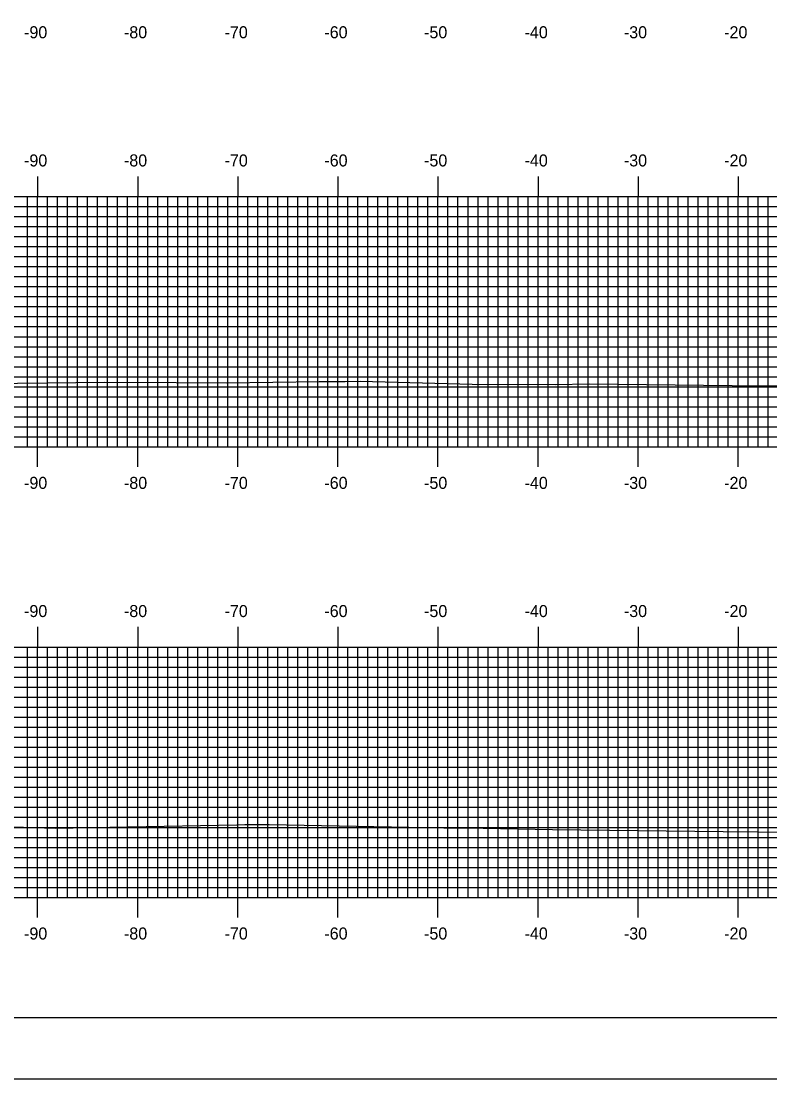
# Model space of a CAD drawing. Extents: x 856323 to 856666, y 364765 to 364985.
# Drawn here: x 856397.1 to 856471.9, y 364765.2 to 364870.8 of the extents above; entities that cross this region are included whole.
import ezdxf

# ---------------------------------------------------------------- set-up
doc = ezdxf.new("R2010")
doc.units = 0
for name, color, linetype in [('BORDER', 7, 'Continuous'), ('H_V ANNOTATION', 7, 'Continuous'), ('MAJOR', 7, 'Continuous'), ('MINOR', 7, 'Continuous'), ('PLOT BOUNDARY', 7, 'Continuous'), ('S_Roadway_Centerline', 7, 'Continuous')]:
    doc.layers.add(name, color=color, linetype=linetype)

msp = doc.modelspace()

# ---------------------------------------------------------------- linework, layer by layer
at = {"layer": 'BORDER'}
msp.add_lwpolyline([(856339.17, 364771.3), (856659.17, 364771.3), (856659.17, 364981.3), (856339.17, 364981.3)], close=True, dxfattribs=at)
at = {"layer": 'MAJOR'}
for p, q in [((856398.77, 364855.31), (856398.77, 364853.3)), ((856408.77, 364855.31), (856408.77, 364853.3)), ((856418.77, 364855.31), (856418.77, 364853.3)), ((856428.77, 364855.31), (856428.77, 364853.3)), ((856438.77, 364855.31), (856438.77, 364853.3)), ((856448.77, 364855.31), (856448.77, 364853.3)), ((856458.77, 364855.31), (856458.77, 364853.3)), ((856468.77, 364855.31), (856468.77, 364853.3)), ((856348.77, 364853.3), (856628.77, 364853.3)), ((856348.77, 364853.3), (856628.77, 364853.3)), ((856398.77, 364828.3), (856398.77, 364853.3)), ((856408.77, 364828.3), (856408.77, 364853.3)), ((856418.77, 364828.3), (856418.77, 364853.3)), ((856428.77, 364828.3), (856428.77, 364853.3)), ((856438.77, 364828.3), (856438.77, 364853.3)), ((856448.77, 364828.3), (856448.77, 364853.3)), ((856458.77, 364828.3), (856458.77, 364853.3)), ((856468.77, 364828.3), (856468.77, 364853.3)), ((856348.77, 364848.3), (856628.77, 364848.3)), ((856348.77, 364843.3), (856628.77, 364843.3)), ((856348.77, 364838.3), (856628.77, 364838.3)), ((856348.77, 364833.3), (856628.77, 364833.3)), ((856348.77, 364828.3), (856628.77, 364828.3)), ((856348.77, 364828.3), (856628.77, 364828.3)), ((856398.77, 364826.3), (856398.77, 364828.3)), ((856408.77, 364826.3), (856408.77, 364828.3)), ((856418.77, 364826.3), (856418.77, 364828.3)), ((856428.77, 364826.3), (856428.77, 364828.3)), ((856438.77, 364826.3), (856438.77, 364828.3)), ((856448.77, 364826.3), (856448.77, 364828.3)), ((856458.77, 364826.3), (856458.77, 364828.3)), ((856468.77, 364826.3), (856468.77, 364828.3)), ((856398.77, 364810.31), (856398.77, 364808.3)), ((856408.77, 364810.31), (856408.77, 364808.3)), ((856418.77, 364810.31), (856418.77, 364808.3)), ((856428.77, 364810.31), (856428.77, 364808.3)), ((856438.77, 364810.31), (856438.77, 364808.3)), ((856448.77, 364810.31), (856448.77, 364808.3)), ((856458.77, 364810.31), (856458.77, 364808.3)), ((856468.77, 364810.31), (856468.77, 364808.3)), ((856348.77, 364808.3), (856628.77, 364808.3)), ((856348.77, 364808.3), (856628.77, 364808.3)), ((856398.77, 364783.3), (856398.77, 364808.3)), ((856408.77, 364783.3), (856408.77, 364808.3)), ((856418.77, 364783.3), (856418.77, 364808.3)), ((856428.77, 364783.3), (856428.77, 364808.3)), ((856438.77, 364783.3), (856438.77, 364808.3)), ((856448.77, 364783.3), (856448.77, 364808.3)), ((856458.77, 364783.3), (856458.77, 364808.3)), ((856468.77, 364783.3), (856468.77, 364808.3)), ((856348.77, 364803.3), (856628.77, 364803.3)), ((856348.77, 364798.3), (856628.77, 364798.3)), ((856348.77, 364793.3), (856628.77, 364793.3)), ((856348.77, 364788.3), (856628.77, 364788.3)), ((856348.77, 364783.3), (856628.77, 364783.3)), ((856348.77, 364783.3), (856628.77, 364783.3)), ((856398.77, 364781.3), (856398.77, 364783.3)), ((856408.77, 364781.3), (856408.77, 364783.3)), ((856418.77, 364781.3), (856418.77, 364783.3)), ((856428.77, 364781.3), (856428.77, 364783.3)), ((856438.77, 364781.3), (856438.77, 364783.3)), ((856448.77, 364781.3), (856448.77, 364783.3)), ((856458.77, 364781.3), (856458.77, 364783.3)), ((856468.77, 364781.3), (856468.77, 364783.3))]:
    msp.add_line(p, q, dxfattribs=at)
at = {"layer": 'MINOR'}
for p, q in [((856397.77, 364828.3), (856397.77, 364853.3)), ((856399.77, 364828.3), (856399.77, 364853.3)), ((856400.77, 364828.3), (856400.77, 364853.3)), ((856401.77, 364828.3), (856401.77, 364853.3)), ((856402.77, 364828.3), (856402.77, 364853.3)), ((856403.77, 364828.3), (856403.77, 364853.3)), ((856404.77, 364828.3), (856404.77, 364853.3)), ((856405.77, 364828.3), (856405.77, 364853.3)), ((856406.77, 364828.3), (856406.77, 364853.3)), ((856407.77, 364828.3), (856407.77, 364853.3)), ((856409.77, 364828.3), (856409.77, 364853.3)), ((856410.77, 364828.3), (856410.77, 364853.3)), ((856411.77, 364828.3), (856411.77, 364853.3)), ((856412.77, 364828.3), (856412.77, 364853.3)), ((856413.77, 364828.3), (856413.77, 364853.3)), ((856414.77, 364828.3), (856414.77, 364853.3)), ((856415.77, 364828.3), (856415.77, 364853.3)), ((856416.77, 364828.3), (856416.77, 364853.3)), ((856417.77, 364828.3), (856417.77, 364853.3)), ((856419.77, 364828.3), (856419.77, 364853.3)), ((856420.77, 364828.3), (856420.77, 364853.3)), ((856421.77, 364828.3), (856421.77, 364853.3)), ((856422.77, 364828.3), (856422.77, 364853.3)), ((856423.77, 364828.3), (856423.77, 364853.3)), ((856424.77, 364828.3), (856424.77, 364853.3)), ((856425.77, 364828.3), (856425.77, 364853.3)), ((856426.77, 364828.3), (856426.77, 364853.3)), ((856427.77, 364828.3), (856427.77, 364853.3)), ((856429.77, 364828.3), (856429.77, 364853.3)), ((856430.77, 364828.3), (856430.77, 364853.3)), ((856431.77, 364828.3), (856431.77, 364853.3)), ((856432.77, 364828.3), (856432.77, 364853.3)), ((856433.77, 364828.3), (856433.77, 364853.3)), ((856434.77, 364828.3), (856434.77, 364853.3)), ((856435.77, 364828.3), (856435.77, 364853.3)), ((856436.77, 364828.3), (856436.77, 364853.3)), ((856437.77, 364828.3), (856437.77, 364853.3)), ((856439.77, 364828.3), (856439.77, 364853.3)), ((856440.77, 364828.3), (856440.77, 364853.3)), ((856441.77, 364828.3), (856441.77, 364853.3)), ((856442.77, 364828.3), (856442.77, 364853.3)), ((856443.77, 364828.3), (856443.77, 364853.3)), ((856444.77, 364828.3), (856444.77, 364853.3)), ((856445.77, 364828.3), (856445.77, 364853.3)), ((856446.77, 364828.3), (856446.77, 364853.3)), ((856447.77, 364828.3), (856447.77, 364853.3)), ((856449.77, 364828.3), (856449.77, 364853.3)), ((856450.77, 364828.3), (856450.77, 364853.3)), ((856451.77, 364828.3), (856451.77, 364853.3)), ((856452.77, 364828.3), (856452.77, 364853.3)), ((856453.77, 364828.3), (856453.77, 364853.3)), ((856454.77, 364828.3), (856454.77, 364853.3)), ((856455.77, 364828.3), (856455.77, 364853.3)), ((856456.77, 364828.3), (856456.77, 364853.3)), ((856457.77, 364828.3), (856457.77, 364853.3)), ((856459.77, 364828.3), (856459.77, 364853.3)), ((856460.77, 364828.3), (856460.77, 364853.3)), ((856461.77, 364828.3), (856461.77, 364853.3)), ((856462.77, 364828.3), (856462.77, 364853.3)), ((856463.77, 364828.3), (856463.77, 364853.3)), ((856464.77, 364828.3), (856464.77, 364853.3)), ((856465.77, 364828.3), (856465.77, 364853.3)), ((856466.77, 364828.3), (856466.77, 364853.3)), ((856467.77, 364828.3), (856467.77, 364853.3)), ((856469.77, 364828.3), (856469.77, 364853.3)), ((856470.77, 364828.3), (856470.77, 364853.3)), ((856471.77, 364828.3), (856471.77, 364853.3)), ((856348.77, 364852.3), (856628.77, 364852.3)), ((856348.77, 364851.3), (856628.77, 364851.3)), ((856348.77, 364850.3), (856628.77, 364850.3)), ((856348.77, 364849.3), (856628.77, 364849.3)), ((856348.77, 364847.3), (856628.77, 364847.3)), ((856348.77, 364846.3), (856628.77, 364846.3)), ((856348.77, 364845.3), (856628.77, 364845.3)), ((856348.77, 364844.3), (856628.77, 364844.3)), ((856348.77, 364842.3), (856628.77, 364842.3)), ((856348.77, 364841.3), (856628.77, 364841.3)), ((856348.77, 364840.3), (856628.77, 364840.3)), ((856348.77, 364839.3), (856628.77, 364839.3)), ((856348.77, 364837.3), (856628.77, 364837.3)), ((856348.77, 364836.3), (856628.77, 364836.3)), ((856348.77, 364835.3), (856628.77, 364835.3)), ((856348.77, 364834.3), (856628.77, 364834.3)), ((856348.77, 364832.3), (856628.77, 364832.3)), ((856348.77, 364831.3), (856628.77, 364831.3)), ((856348.77, 364830.3), (856628.77, 364830.3)), ((856348.77, 364829.3), (856628.77, 364829.3)), ((856397.77, 364783.3), (856397.77, 364808.3)), ((856399.77, 364783.3), (856399.77, 364808.3)), ((856400.77, 364783.3), (856400.77, 364808.3)), ((856401.77, 364783.3), (856401.77, 364808.3)), ((856402.77, 364783.3), (856402.77, 364808.3)), ((856403.77, 364783.3), (856403.77, 364808.3)), ((856404.77, 364783.3), (856404.77, 364808.3)), ((856405.77, 364783.3), (856405.77, 364808.3)), ((856406.77, 364783.3), (856406.77, 364808.3)), ((856407.77, 364783.3), (856407.77, 364808.3)), ((856409.77, 364783.3), (856409.77, 364808.3)), ((856410.77, 364783.3), (856410.77, 364808.3)), ((856411.77, 364783.3), (856411.77, 364808.3)), ((856412.77, 364783.3), (856412.77, 364808.3)), ((856413.77, 364783.3), (856413.77, 364808.3)), ((856414.77, 364783.3), (856414.77, 364808.3)), ((856415.77, 364783.3), (856415.77, 364808.3)), ((856416.77, 364783.3), (856416.77, 364808.3)), ((856417.77, 364783.3), (856417.77, 364808.3)), ((856419.77, 364783.3), (856419.77, 364808.3)), ((856420.77, 364783.3), (856420.77, 364808.3)), ((856421.77, 364783.3), (856421.77, 364808.3)), ((856422.77, 364783.3), (856422.77, 364808.3)), ((856423.77, 364783.3), (856423.77, 364808.3)), ((856424.77, 364783.3), (856424.77, 364808.3)), ((856425.77, 364783.3), (856425.77, 364808.3)), ((856426.77, 364783.3), (856426.77, 364808.3)), ((856427.77, 364783.3), (856427.77, 364808.3)), ((856429.77, 364783.3), (856429.77, 364808.3)), ((856430.77, 364783.3), (856430.77, 364808.3)), ((856431.77, 364783.3), (856431.77, 364808.3)), ((856432.77, 364783.3), (856432.77, 364808.3)), ((856433.77, 364783.3), (856433.77, 364808.3)), ((856434.77, 364783.3), (856434.77, 364808.3)), ((856435.77, 364783.3), (856435.77, 364808.3)), ((856436.77, 364783.3), (856436.77, 364808.3)), ((856437.77, 364783.3), (856437.77, 364808.3)), ((856439.77, 364783.3), (856439.77, 364808.3)), ((856440.77, 364783.3), (856440.77, 364808.3)), ((856441.77, 364783.3), (856441.77, 364808.3)), ((856442.77, 364783.3), (856442.77, 364808.3)), ((856443.77, 364783.3), (856443.77, 364808.3)), ((856444.77, 364783.3), (856444.77, 364808.3)), ((856445.77, 364783.3), (856445.77, 364808.3)), ((856446.77, 364783.3), (856446.77, 364808.3)), ((856447.77, 364783.3), (856447.77, 364808.3)), ((856449.77, 364783.3), (856449.77, 364808.3)), ((856450.77, 364783.3), (856450.77, 364808.3)), ((856451.77, 364783.3), (856451.77, 364808.3)), ((856452.77, 364783.3), (856452.77, 364808.3)), ((856453.77, 364783.3), (856453.77, 364808.3)), ((856454.77, 364783.3), (856454.77, 364808.3)), ((856455.77, 364783.3), (856455.77, 364808.3)), ((856456.77, 364783.3), (856456.77, 364808.3)), ((856457.77, 364783.3), (856457.77, 364808.3)), ((856459.77, 364783.3), (856459.77, 364808.3)), ((856460.77, 364783.3), (856460.77, 364808.3)), ((856461.77, 364783.3), (856461.77, 364808.3)), ((856462.77, 364783.3), (856462.77, 364808.3)), ((856463.77, 364783.3), (856463.77, 364808.3)), ((856464.77, 364783.3), (856464.77, 364808.3)), ((856465.77, 364783.3), (856465.77, 364808.3)), ((856466.77, 364783.3), (856466.77, 364808.3)), ((856467.77, 364783.3), (856467.77, 364808.3)), ((856469.77, 364783.3), (856469.77, 364808.3)), ((856470.77, 364783.3), (856470.77, 364808.3)), ((856471.77, 364783.3), (856471.77, 364808.3)), ((856348.77, 364807.3), (856628.77, 364807.3)), ((856348.77, 364806.3), (856628.77, 364806.3)), ((856348.77, 364805.3), (856628.77, 364805.3)), ((856348.77, 364804.3), (856628.77, 364804.3)), ((856348.77, 364802.3), (856628.77, 364802.3)), ((856348.77, 364801.3), (856628.77, 364801.3)), ((856348.77, 364800.3), (856628.77, 364800.3)), ((856348.77, 364799.3), (856628.77, 364799.3)), ((856348.77, 364797.3), (856628.77, 364797.3)), ((856348.77, 364796.3), (856628.77, 364796.3)), ((856348.77, 364795.3), (856628.77, 364795.3)), ((856348.77, 364794.3), (856628.77, 364794.3)), ((856348.77, 364792.3), (856628.77, 364792.3)), ((856348.77, 364791.3), (856628.77, 364791.3)), ((856348.77, 364790.3), (856628.77, 364790.3)), ((856348.77, 364789.3), (856628.77, 364789.3)), ((856348.77, 364787.3), (856628.77, 364787.3)), ((856348.77, 364786.3), (856628.77, 364786.3)), ((856348.77, 364785.3), (856628.77, 364785.3)), ((856348.77, 364784.3), (856628.77, 364784.3))]:
    msp.add_line(p, q, dxfattribs=at)
at = {"layer": 'PLOT BOUNDARY'}
msp.add_lwpolyline([(856322.98, 364765.18), (856662.98, 364765.18), (856662.98, 364985.18), (856322.98, 364985.18)], close=True, dxfattribs=at)
at = {"layer": 'S_Roadway_Centerline'}
for points in [[(856348.77, 364835.2), (856349.82, 364835.18), (856356.1, 364835.04), (856357.68, 364835.05), (856360.49, 364834.98), (856374.89, 364834.82), (856381.34, 364834.91), (856393.54, 364834.63), (856393.73, 364834.63), (856393.83, 364834.63), (856405.49, 364834.77), (856412.6, 364834.72), (856417.64, 364834.68), (856426.89, 364834.83), (856429.49, 364834.84), (856430.99, 364834.85), (856442.18, 364834.56), (856450.47, 364834.52), (856453.9, 364834.6), (856468.17, 364834.44), (856477.63, 364834.39)], [(856348.77, 364790.65), (856355.76, 364790.63), (856359.66, 364790.58), (856362.04, 364790.55), (856371, 364790.35), (856380.8, 364790.18), (856387.05, 364790.22), (856395.28, 364790.4), (856400.54, 364790.23), (856418.69, 364790.56), (856419.47, 364790.58), (856419.95, 364790.59), (856421.91, 364790.57), (856439.36, 364790.26), (856443.27, 364790.21), (856450.21, 364790.1), (856467.25, 364789.88), (856481.4, 364789.74)]]:
    msp.add_lwpolyline(points, dxfattribs=at)

# ---------------------------------------------------------------- texts
at = {"layer": 'H_V ANNOTATION'}
for s, p in [('-90', (856397.42, 364869.1)), ('-80', (856407.4, 364869.1)), ('-70', (856417.45, 364869.1)), ('-60', (856427.42, 364869.1)), ('-50', (856437.38, 364869.1)), ('-40', (856447.42, 364869.1)), ('-30', (856457.34, 364869.1)), ('-20', (856467.36, 364869.1)), ('-90', (856397.42, 364856.3)), ('-80', (856407.4, 364856.3)), ('-70', (856417.45, 364856.3)), ('-60', (856427.42, 364856.3)), ('-50', (856437.38, 364856.3)), ('-40', (856447.42, 364856.3)), ('-30', (856457.34, 364856.3)), ('-20', (856467.36, 364856.3)), ('-90', (856397.42, 364824.1)), ('-80', (856407.4, 364824.1)), ('-70', (856417.45, 364824.1)), ('-60', (856427.42, 364824.1)), ('-50', (856437.38, 364824.1)), ('-40', (856447.42, 364824.1)), ('-30', (856457.34, 364824.1)), ('-20', (856467.36, 364824.1)), ('-90', (856397.42, 364811.3)), ('-80', (856407.4, 364811.3)), ('-70', (856417.45, 364811.3)), ('-60', (856427.42, 364811.3)), ('-50', (856437.38, 364811.3)), ('-40', (856447.42, 364811.3)), ('-30', (856457.34, 364811.3)), ('-20', (856467.36, 364811.3)), ('-90', (856397.42, 364779.1)), ('-80', (856407.4, 364779.1)), ('-70', (856417.45, 364779.1)), ('-60', (856427.42, 364779.1)), ('-50', (856437.38, 364779.1)), ('-40', (856447.42, 364779.1)), ('-30', (856457.34, 364779.1)), ('-20', (856467.36, 364779.1))]:
    msp.add_text(s, height=1.2, dxfattribs=at).set_placement(p)

doc.saveas('drawing.dxf')
